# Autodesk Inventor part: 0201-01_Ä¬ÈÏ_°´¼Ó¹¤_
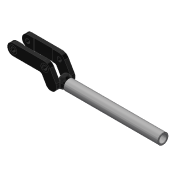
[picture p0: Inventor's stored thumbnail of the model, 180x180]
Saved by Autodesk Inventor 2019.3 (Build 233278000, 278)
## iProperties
Created: 2010-06
Part Number: 0201-01_Ä¬ÈÏ_°´¼Ó¹¤_
Material: Ogólny
Document SubType Name: Modeling
Designer: CADENGINEERING4
Density: 1 g/cm^3
Appearance: Gładki — czarny
Author: CADENGINEERING4
Revision Number: ÈÎºÎ
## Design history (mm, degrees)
feature "NONE"
feature "NONE:1"
node "Bryła1"
node "Bryła2"
